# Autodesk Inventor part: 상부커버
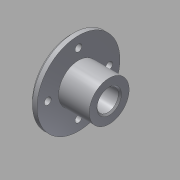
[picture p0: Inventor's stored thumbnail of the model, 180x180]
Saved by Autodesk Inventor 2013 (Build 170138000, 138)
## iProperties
Created: 2015-09
Part Number: 상부커버
Material: 알루미늄 6061
Document SubType Name: Modeling
Designer: mduedu
Density: 1 g/cm^3
Author: mduedu
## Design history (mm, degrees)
sketch "스케치1"
  geometry: L1 (-12.5, 0)-(12.5, 0); L2 (-12.5, 0)-(-12.5, 27); L3 (-12.5, 27)-(-7.5, 27); L4 (-7.5, 27)-(-7.5, 13); L5 (-7.5, 13)-(12.5, 13); L6 (12.5, 13)-(12.5, 0); 2 further points
  constraints: 12 end point, 2 parallel, 2 perpendicular, 1 coincident, 1 horizontal, 1 midpoint, 1 vertical
  dimensions: "d0" = 25 distance of L1.start L1.end; "d2" = 5 distance of L2.end L3.end; "d3" = 26 diameter of L5 L1; "d4" = 54 diameter of L3 L1
revolve "회전1" sketch "스케치1" stored, may be unused: angle "d5" = 90 deg
hole "구멍1" diameter "d8" = 14; stored, may be unused: countersink angle "d12" = 90 deg, drill point angle "d14" = 118 deg; dims "d6" = 10, "d7" = 10, "d9" = 6, "d10" = 4, "d11" = 2, "d13" = 8
chamfer "모따기1" distance "d15" = 1; stored, may be unused: second distance "d16" = 2, angle "d17" = 45 deg
chamfer "모따기2" distance "d18" = 2; stored, may be unused: second distance "d19" = 2, angle "d20" = 45 deg
sketch "스케치2" dims "d21" = 40
  geometry: 6 further points
  constraints: 2 vertical alignment, 1 coincident, 7 other
  dimensions: "d25" = 360 deg dimension on point (0, 0) point (0, 20) (derived)
sketch "스케치3"
  geometry: 4 further points
hole "구멍2" sketch "스케치3" at (0, 20), (-20, 0), (20, 0), (0, -20) diameter "d27" = 4.5; stored, may be unused: countersink angle "d31" = 90 deg, drill point angle "d33" = 0 deg; dims "d28" = 6, "d29" = 4, "d30" = 2, "d32" = 8
node "솔리드1"
